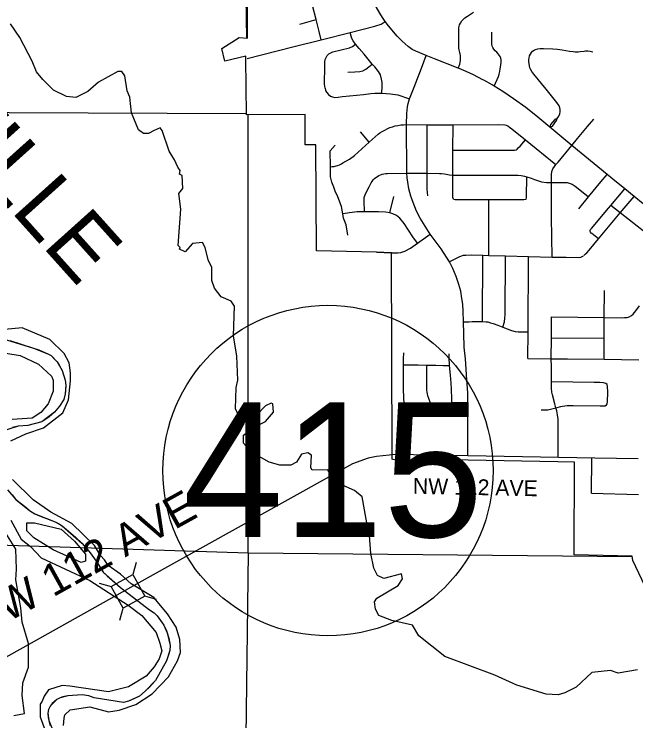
# Model space of a CAD drawing. Extents: x -1403959 to 81668, y -1400582 to 11018.
# Drawn here: x 6553.7 to 6705.6, y 9361 to 9533.5 of the extents above; entities that cross this region are included whole.
import ezdxf

# ---------------------------------------------------------------- set-up
doc = ezdxf.new("R2010")
doc.units = 0
for name, color, linetype in [('tdCiCityCartoExten', 7, 'Continuous'), ('tdCiCityStreetTxt', 7, 'Continuous'), ('tdCiRRCL', 7, 'Continuous'), ('tdCiSectNmbr', 7, 'Continuous'), ('tdCiSectTwpRng', 7, 'Continuous'), ('tdCoCityStreetMajor', 7, 'Continuous'), ('tdCoClipBndry', 7, 'Continuous'), ('tdCoSecRteCL', 7, 'Continuous'), ('tdCoSectNmbr', 7, 'Continuous'), ('tdCoSurfAsphalt', 7, 'Continuous'), ('tdCoSurfBitum', 7, 'Continuous'), ('tdCoSurfConc', 7, 'Continuous'), ('tdCoTwpNameTxt', 7, 'Continuous')]:
    doc.layers.add(name, color=color, linetype=linetype)

msp = doc.modelspace()

# ---------------------------------------------------------------- linework, layer by layer
at = {"layer": 'tdCiCityCartoExten'}
msp.add_lwpolyline([(6642.22, 9475.37), (6645.91, 9475.25)], dxfattribs=at)
at = {"layer": 'tdCiCityStreetTxt'}
for points in [[(6583.49, 9399.66), (6582.67, 9396.75), (6585.62, 9391.47)], [(6574.47, 9394.63), (6577.38, 9393.8), (6582.67, 9396.75)], [(6579.51, 9385.61), (6580.33, 9388.52), (6577.38, 9393.8)], [(6588.47, 9390.66), (6585.62, 9391.47), (6580.33, 9388.52)]]:
    msp.add_lwpolyline(points, dxfattribs=at)
at = {"layer": 'tdCiRRCL'}
msp.add_lwpolyline([(6707.74, 9393.96), (6704.85, 9400.15), (6704.66, 9401.18), (6690.47, 9401.55), (6690.57, 9424.12), (6686.52, 9424.19), (6664.56, 9424.61), (6651.55, 9424.86), (6650.83, 9423.48), (6646.06, 9424.86), (6646.06, 9425.97), (6645.91, 9475.25), (6642.22, 9475.37), (6627.57, 9475.76), (6627.42, 9501.63), (6624.83, 9501.64), (6624.78, 9509.01), (6610.44, 9508.89), (6610.32, 9522.61), (6610.31, 9523.23), (6605.15, 9522.02), (6604.42, 9525.13), (6608.68, 9527.76), (6610.67, 9527.64), (6610.74, 9565.24)], dxfattribs=at)
at = {"layer": 'tdCiSectNmbr'}
for points in [[(6644.37, 9531.72), (6643.86, 9532.43), (6643.31, 9533.31), (6641.35, 9536.66), (6639.96, 9539.04), (6638.83, 9540.49), (6637.41, 9542.06), (6634.5, 9544.62), (6632.79, 9546.21), (6631.47, 9547.73), (6630.64, 9549.07), (6629.81, 9550.83), (6629.23, 9552.48), (6628.94, 9553.79), (6628.79, 9554.95), (6628.69, 9556.1), (6628.65, 9559.75), (6628.66, 9562.74), (6628.73, 9577.13), (6628.79, 9589.35), (6628.81, 9591.2), (6628.8, 9591.55)], [(6654.33, 9523.38), (6651.83, 9524.45), (6650.94, 9524.91), (6649.97, 9525.58), (6648.46, 9526.88), (6647.23, 9528.16), (6645.17, 9530.62), (6644.37, 9531.72)], [(6653.19, 9520.28), (6654.33, 9523.38)], [(6665.88, 9518.69), (6664.09, 9519.51), (6662.4, 9520.24), (6662.17, 9520.33), (6656.37, 9522.59), (6654.33, 9523.37)], [(6649.62, 9509.26), (6649.81, 9510.89), (6649.94, 9511.67), (6650.24, 9512.83), (6651.4, 9515.7), (6653.19, 9520.28)], [(6715.01, 9480.92), (6709.53, 9485.4), (6705.13, 9488.95), (6702.82, 9490.86), (6699.89, 9493.25), (6698.55, 9494.37), (6689.91, 9501.43), (6684.54, 9505.9), (6681.62, 9508.34), (6678.66, 9510.71), (6675.69, 9512.86), (6673.04, 9514.63), (6670.91, 9515.95), (6670.5, 9516.21), (6668.4, 9517.36), (6668.17, 9517.47), (6665.88, 9518.69)], [(6664.49, 9425.7), (6664.52, 9437.42), (6664.49, 9441.03), (6664.31, 9444.24), (6663.91, 9449.39), (6663.65, 9452.23), (6663.52, 9455.58), (6663.43, 9458.38), (6663.38, 9461.01), (6663.27, 9462.74), (6663.09, 9464.13), (6662.79, 9465.86), (6662.36, 9467.48), (6661.68, 9469.48), (6660.84, 9471.41), (6660.03, 9473.08), (6657.97, 9476.21), (6655.36, 9479.83), (6654.09, 9481.76), (6652.9, 9483.67), (6651.98, 9485.41), (6651.15, 9487.49), (6650.59, 9489.11), (6650.11, 9490.84), (6649.85, 9492.46), (6649.68, 9493.58), (6649.6, 9494.65), (6649.52, 9506.54), (6649.62, 9509.26)], [(6645.91, 9475.25), (6647.46, 9475.2), (6648.13, 9475.32), (6649.15, 9475.65), (6650.52, 9476.38), (6652.25, 9477.61), (6655.36, 9479.83)]]:
    msp.add_lwpolyline(points, dxfattribs=at)
at = {"layer": 'tdCiSectTwpRng'}
for points in [[(6628.67, 9527.26), (6628.18, 9529.25), (6627.49, 9532.17), (6626.6, 9535.6), (6625.93, 9538.31), (6624.97, 9541.95), (6624.63, 9543.49), (6624.49, 9544.59), (6624.42, 9545.56), (6624.42, 9546.66), (6624.51, 9547.64), (6624.61, 9548.9), (6624.73, 9550.29), (6624.73, 9551.15), (6624.75, 9554.68), (6624.88, 9565.47), (6624.88, 9577.21)], [(6662.17, 9520.33), (6662.55, 9521.32), (6662.65, 9521.73), (6662.73, 9522.3), (6662.74, 9522.81), (6662.7, 9523.43), (6662.59, 9524.1), (6662.4, 9524.78), (6662.33, 9525.17), (6662.32, 9525.82), (6662.32, 9529.65), (6662.32, 9530.06), (6662.42, 9530.6), (6662.51, 9530.88), (6662.72, 9531.32), (6663.04, 9531.86), (6663.36, 9532.19), (6663.82, 9532.61), (6664.43, 9533), (6665.93, 9533.99)], [(6610.66, 9522.7), (6621.79, 9525.54), (6628.67, 9527.26), (6635.78, 9529.04), (6641.84, 9530.57), (6643.32, 9531.09), (6644.37, 9531.72)], [(6623.51, 9531.03), (6627.49, 9532.17)], [(6670.91, 9515.95), (6671.98, 9518.28), (6672.17, 9518.81), (6672.32, 9519.48), (6672.43, 9520.16), (6672.55, 9521.03), (6672.63, 9521.82), (6672.63, 9522.33), (6672.55, 9522.75), (6672.4, 9523.19), (6672.21, 9523.52), (6671.96, 9523.79), (6671.57, 9524.2), (6671.17, 9524.56), (6670.83, 9524.97), (6670.62, 9525.36), (6670.5, 9525.69), (6670.42, 9526.15), (6670.41, 9527.54), (6670.42, 9529.14)], [(6643.49, 9514.23), (6643.63, 9515.94), (6643.59, 9516.84), (6643.46, 9517.67), (6643.17, 9518.66), (6642.68, 9519.48), (6641.8, 9520.6), (6641.19, 9521.3), (6639.23, 9523.7), (6638.02, 9525.12), (6637.11, 9526.14), (6636.51, 9527), (6636.21, 9527.53), (6636.02, 9528.09), (6635.78, 9529.04)], [(6629.56, 9520.79), (6629.57, 9521.85), (6629.66, 9522.41), (6629.9, 9522.94), (6630.19, 9523.41), (6630.59, 9523.78), (6631.04, 9524.08), (6631.59, 9524.3), (6635.65, 9525.3), (6636.36, 9525.58), (6637.11, 9526.14)], [(6686.32, 9508.04), (6686.73, 9508.61), (6686.98, 9509.16), (6687.09, 9509.69), (6687.09, 9510.21), (6687.02, 9510.67), (6686.83, 9511.14), (6686.26, 9511.95), (6683.64, 9515.16), (6680.66, 9518.82), (6680.16, 9519.5), (6679.83, 9520.04), (6679.67, 9520.43), (6679.54, 9520.91), (6679.46, 9521.45), (6679.42, 9521.88), (6679.42, 9522.37), (6679.47, 9522.87), (6679.6, 9523.32), (6679.79, 9523.74), (6680.06, 9524.15), (6680.33, 9524.44), (6680.68, 9524.72), (6681.03, 9524.88), (6681.61, 9525.07), (6682.16, 9525.13), (6683.01, 9525.12), (6685.24, 9525.03), (6686.4, 9524.94), (6687.52, 9524.8), (6688.48, 9524.63), (6689.33, 9524.5), (6690.22, 9524.38), (6690.77, 9524.33), (6691.47, 9524.33), (6691.97, 9524.35), (6692.9, 9524.46), (6693.25, 9524.52), (6693.82, 9524.52), (6694.42, 9524.48), (6695.05, 9524.29)], [(6695.05, 9524.29), (6695.08, 9524.28)], [(6629.64, 9515.47), (6629.51, 9516.4), (6629.56, 9520.79)], [(6635.19, 9519.37), (6636.95, 9519.44), (6638.12, 9519.49), (6638.91, 9519.69), (6639.58, 9520.05), (6640.37, 9520.64), (6641.19, 9521.3)], [(6629.64, 9515.47), (6629.78, 9514.89), (6629.98, 9514.46), (6630.49, 9513.87), (6631, 9513.51), (6631.5, 9513.32), (6632.02, 9513.18), (6632.83, 9513.26), (6633.91, 9513.37), (6639.01, 9513.92), (6640.79, 9514.12), (6641.79, 9514.23), (6643.49, 9514.23), (6645.66, 9514.02), (6647.44, 9513.78), (6650.24, 9512.83)], [(6686.32, 9508.04), (6685.76, 9507.8), (6684.67, 9506.54), (6684.54, 9505.9)], [(6684.56, 9505.91), (6685.19, 9506.19), (6686.21, 9507.54), (6686.32, 9508.04)], [(6689.91, 9501.43), (6691.33, 9503.15), (6693.74, 9506.07), (6695.31, 9507.86)], [(6630.95, 9496.26), (6631.41, 9496.29), (6631.88, 9496.35), (6632.33, 9496.45), (6632.78, 9496.59), (6633.21, 9496.76), (6633.63, 9496.96), (6634.03, 9497.2), (6635.61, 9498.09), (6636.88, 9499), (6640.44, 9502.23), (6642.64, 9504.18), (6643.06, 9504.49), (6643.63, 9504.88), (6644.22, 9505.22), (6644.84, 9505.53), (6645.47, 9505.8), (6646.12, 9506.03), (6646.79, 9506.22), (6647.46, 9506.36), (6648.14, 9506.47), (6648.83, 9506.52), (6649.52, 9506.54)], [(6649.54, 9506.54), (6654.56, 9506.52), (6658.13, 9506.51)], [(6654.76, 9489.12), (6654.59, 9490.82), (6654.57, 9494.67), (6654.58, 9500.61), (6654.56, 9506.46)], [(6658.13, 9506.51), (6660.91, 9506.51), (6672.09, 9506.53), (6673.55, 9506.51), (6673.92, 9506.44), (6674.3, 9506.27), (6674.73, 9505.95), (6675.26, 9505.52), (6678.57, 9502.84), (6686.05, 9496.81)], [(6661.04, 9488.36), (6660.89, 9488.74), (6660.86, 9489.24), (6660.86, 9494.22), (6660.85, 9500.31), (6660.91, 9506.51)], [(6684.54, 9505.9), (6684.56, 9505.91)], [(6640.44, 9502.23), (6638.33, 9504.74)], [(6635.24, 9479.59), (6634.77, 9482.08), (6634.16, 9483.7), (6634.02, 9484.76), (6633.68, 9486.54), (6632.76, 9488.87), (6632.15, 9490.27), (6631.76, 9491.27), (6631.31, 9492.51), (6630.97, 9493.8), (6630.95, 9496.26), (6630.92, 9500.14), (6632.09, 9501.5)], [(6660.85, 9500.31), (6675.37, 9500.26), (6675.92, 9500.3), (6676.29, 9500.35), (6676.6, 9500.55), (6676.84, 9500.83), (6677.27, 9501.3), (6678.57, 9502.84)], [(6685.1, 9474.21), (6684.98, 9483.93), (6684.94, 9486.33), (6684.96, 9492.4), (6684.93, 9494.37), (6685.05, 9495.09), (6685.28, 9495.74), (6685.65, 9496.33), (6686.05, 9496.81), (6686.54, 9497.36), (6689.91, 9501.43)], [(6639.17, 9488), (6639.23, 9488.71), (6639.54, 9489.65), (6640.4, 9491.33), (6640.92, 9492.32), (6641.16, 9492.69), (6641.43, 9493.03), (6641.73, 9493.35), (6642.06, 9493.63), (6642.42, 9493.89), (6642.79, 9494.11), (6643.19, 9494.29), (6643.6, 9494.44), (6644.03, 9494.55), (6644.46, 9494.61), (6644.9, 9494.64), (6649.6, 9494.65)], [(6649.65, 9494.65), (6654.57, 9494.67), (6657.56, 9494.62)], [(6657.56, 9494.62), (6658.08, 9494.61), (6658.83, 9494.56), (6660.01, 9494.3), (6660.86, 9494.22), (6676.76, 9494.2), (6677.58, 9494.11), (6678.37, 9493.99), (6678.96, 9493.81), (6680.01, 9493.43), (6680.83, 9493.12), (6682.52, 9492.59), (6683.71, 9492.44), (6684.96, 9492.4), (6688.2, 9492.4), (6688.75, 9492.39), (6689.3, 9492.25), (6690.02, 9491.98), (6690.77, 9491.53), (6691.49, 9490.95), (6694, 9488.89)], [(6678.74, 9488.33), (6678.84, 9488.65), (6678.88, 9489), (6678.96, 9493.81)], [(6691.61, 9485.96), (6694, 9488.89), (6697.01, 9492.61), (6698.55, 9494.37)], [(6694.78, 9479.92), (6694.6, 9480.07), (6694.46, 9480.26), (6694.41, 9480.46), (6694.4, 9480.68), (6694.51, 9480.93), (6694.72, 9481.2), (6698.89, 9486.11), (6699.48, 9486.8), (6702.82, 9490.86)], [(6639.27, 9485.26), (6639.17, 9488)], [(6645.48, 9485.02), (6646.47, 9488.96)], [(6661.04, 9488.36), (6661.46, 9488.24), (6661.95, 9488.22), (6669.64, 9488.23), (6677.74, 9488.22), (6678.22, 9488.23), (6678.74, 9488.33)], [(6669.62, 9474.61), (6669.64, 9488.23)], [(6692.82, 9474.55), (6693.21, 9474.88), (6693.56, 9475.25), (6694.11, 9475.86), (6696.44, 9478.65), (6701.7, 9485.01), (6705.13, 9488.95)], [(6719.41, 9470.65), (6715.54, 9473.82), (6711.88, 9476.99), (6701.7, 9485.01), (6699.48, 9486.8)], [(6634.06, 9484.77), (6634.02, 9484.76)], [(6652.25, 9477.61), (6651.06, 9479.18), (6648.95, 9482.4), (6647.89, 9483.7), (6647.06, 9484.33), (6646.17, 9484.78), (6645.48, 9485.02), (6644.43, 9485.18), (6642.7, 9485.24), (6639.27, 9485.26), (6637.47, 9485.24), (6635.66, 9484.98), (6634.06, 9484.77)], [(6696.44, 9478.65), (6694.78, 9479.92)], [(6660.09, 9473.11), (6662.54, 9474.35), (6663.5, 9474.7), (6664.01, 9474.69), (6665.32, 9474.73), (6668.15, 9474.67)], [(6668.11, 9458.45), (6668.15, 9474.67)], [(6668.15, 9474.67), (6669.62, 9474.61), (6673.68, 9474.53), (6679.31, 9474.36), (6685.1, 9474.21), (6688.55, 9474.18)], [(6673.09, 9457.12), (6673.47, 9458.39), (6673.59, 9459.3), (6673.64, 9460.08), (6673.68, 9474.53)], [(6679.2, 9449.44), (6679.29, 9455.95), (6679.31, 9474.36)], [(6688.55, 9474.18), (6691.63, 9474.13), (6692.09, 9474.18), (6692.43, 9474.31), (6692.79, 9474.52)], [(6697.79, 9449.32), (6697.78, 9454.38), (6697.78, 9459.43), (6697.86, 9466.07)], [(6684.93, 9459.61), (6697.78, 9459.43), (6702.04, 9459.4), (6702.8, 9459.42), (6703.39, 9459.49), (6703.9, 9459.63), (6704.45, 9459.91), (6704.91, 9460.27), (6705.54, 9461.11), (6706.47, 9462.33)], [(6663.43, 9458.38), (6663.6, 9458.39)], [(6663.6, 9458.39), (6664.73, 9458.42)], [(6664.73, 9458.42), (6665.54, 9458.44), (6668.11, 9458.45), (6668.97, 9458.43), (6669.43, 9458.37), (6670.03, 9458.19), (6670.71, 9458.02), (6671.82, 9457.62), (6673.09, 9457.12), (6675.18, 9456.31), (6676.09, 9456.04), (6676.82, 9455.99), (6679.29, 9455.95)], [(6684.84, 9449.38), (6684.97, 9454.51), (6684.93, 9459.61)], [(6684.97, 9454.51), (6697.78, 9454.38)], [(6649.13, 9437.75), (6648.92, 9439.41), (6648.86, 9440.13), (6648.81, 9441.84), (6648.81, 9443.82), (6648.83, 9447.93), (6648.83, 9449.34), (6648.85, 9450.85)], [(6660.61, 9438.15), (6660.6, 9438.67), (6660.61, 9440.24), (6660.57, 9441.2), (6660.55, 9441.96), (6660.46, 9443.44), (6660.3, 9445.36), (6660.08, 9447.77), (6659.96, 9449.77), (6659.92, 9450.62)], [(6679.2, 9449.44), (6684.84, 9449.38)], [(6684.84, 9449.38), (6688.84, 9449.4), (6697.79, 9449.32), (6706.26, 9449.15)], [(6686.54, 9425.29), (6686.59, 9429.83), (6686.59, 9433.48), (6686.54, 9434.67), (6686.45, 9435.69), (6686.23, 9436.7), (6686.04, 9437.42), (6685.78, 9438.39), (6685.21, 9440.54), (6685.06, 9441.2), (6684.94, 9442.23), (6684.94, 9443.04), (6684.95, 9443.73), (6684.97, 9445.05), (6684.92, 9447.48), (6684.84, 9449.38), (6684.84, 9449.38)], [(6648.83, 9447.93), (6650.31, 9447.92), (6652.4, 9447.91), (6654.52, 9447.84), (6656.74, 9447.81), (6658.52, 9447.75), (6660.08, 9447.77)], [(6655.4, 9438.56), (6655, 9439.7), (6654.79, 9440.31), (6654.64, 9440.82), (6654.57, 9441.27), (6654.5, 9441.74), (6654.47, 9442.69), (6654.48, 9446.22), (6654.52, 9447.84)], [(6682.44, 9436.91), (6683.44, 9436.89), (6684.04, 9436.93), (6684.42, 9436.98), (6685.37, 9437.24), (6686.04, 9437.42), (6687.23, 9437.72), (6687.64, 9437.82), (6688.19, 9437.91), (6688.81, 9437.98), (6690.21, 9437.98), (6696.82, 9437.87), (6697.75, 9437.89), (6698.09, 9437.91), (6698.4, 9438.13), (6698.56, 9438.37), (6698.63, 9438.84), (6698.68, 9441.23), (6698.61, 9442.68), (6698.52, 9443.14), (6698.21, 9443.35), (6697.66, 9443.49), (6696.75, 9443.57), (6695.37, 9443.57), (6684.95, 9443.73)], [(6660.6, 9438.67), (6662.44, 9438.67), (6664.51, 9438.67)], [(6694.73, 9416.54), (6694.84, 9425.13)], [(6694.73, 9416.54), (6706.22, 9416.24)]]:
    msp.add_lwpolyline(points, dxfattribs=at)
at = {"layer": 'tdCoCityStreetMajor'}
for points in [[(6610.55, 9527.64), (6609.42, 9597.47)], [(6513.8, 9509.68), (6610.4, 9509.24)], [(6610.87, 9402.01), (6610.86, 9508.39), (6610.85, 9508.9)], [(6511.21, 9405.21), (6610.87, 9402.01)], [(6610.87, 9402.01), (6609.63, 9305.79)], [(6610.87, 9402.01), (6704.63, 9401.12)]]:
    msp.add_lwpolyline(points, dxfattribs=at)
at = {"layer": 'tdCoClipBndry'}
for points in [[(6551.07, 9454.21), (6558.42, 9452.01), (6562.08, 9450.54), (6562.74, 9450.16), (6564.22, 9448.64), (6565.45, 9446.53), (6566.16, 9444.17), (6566.33, 9442.92), (6566.16, 9440.79), (6565.85, 9439.44), (6564.81, 9437.79), (6563.58, 9436.33), (6560.48, 9433.98), (6557.09, 9433.09), (6554.71, 9432.93), (6550.37, 9431.54)], [(6552.09, 9417.41), (6554.16, 9415.04), (6557.51, 9412.32), (6558.75, 9411.54), (6563.72, 9409.58), (6565.43, 9408.64), (6570.27, 9404.4), (6572.08, 9402.33), (6574, 9399.66), (6575.44, 9397.26), (6579.73, 9393.53), (6586.79, 9388.14), (6587.92, 9387.36), (6588.69, 9386.65), (6590.24, 9384.39), (6591.1, 9382.51), (6591.8, 9379.38), (6591.72, 9378.17), (6590.92, 9375.68), (6588.27, 9370.85), (6585.75, 9368.23), (6584.3, 9367.03), (6581.61, 9365.81), (6580.44, 9365.52), (6573.26, 9366.66), (6571.94, 9367.08), (6570.37, 9367.35), (6566.8, 9367.09), (6564.97, 9366.63), (6564.15, 9366.2), (6562.49, 9364.6), (6562.08, 9363.8), (6561.96, 9362.88), (6562.16, 9361.11), (6563.66, 9357.49)]]:
    msp.add_lwpolyline(points, dxfattribs=at)
at = {"layer": 'tdCoSecRteCL'}
msp.add_lwpolyline([(6706.14, 9424.94), (6695.52, 9425.1), (6646.83, 9426.05), (6642.24, 9425.54), (6640.19, 9425.12), (6636.32, 9423.72), (6586.24, 9395.82), (6555.85, 9378.84), (6530.4, 9364.67)], dxfattribs=at)
at = {"layer": 'tdCoSurfAsphalt'}
msp.add_circle((6630.36, 9422.1), 40.33, dxfattribs=at)
at = {"layer": 'tdCoSurfBitum'}
for points in [[(6705.96, 9373.43), (6701.22, 9372.68), (6699.39, 9373.29), (6694.81, 9372.84), (6690.99, 9369.19), (6688.23, 9367.82), (6686.55, 9367.37), (6683.65, 9367.53), (6676.48, 9369.68), (6671.14, 9372.13), (6658.94, 9376.74), (6652.53, 9381.79), (6651.01, 9384.39), (6645.97, 9385.47), (6642.77, 9386.7), (6642.01, 9388.23), (6641.71, 9390.06), (6642.32, 9390.98), (6647.52, 9394.02), (6648.59, 9395.7), (6648.29, 9396.92), (6644.01, 9395.71), (6642.48, 9396.47), (6641.57, 9398.31), (6640.82, 9401.82), (6640.52, 9406.25), (6640.07, 9407.93), (6638.71, 9415.72), (6636.88, 9417.25), (6632.61, 9419.09), (6631.24, 9420.77), (6630.32, 9422.3), (6626.5, 9422.16), (6626.2, 9422.77), (6626.36, 9425.82), (6625.44, 9426.43), (6623.92, 9426.13), (6622.69, 9424.15), (6621.32, 9423.39), (6618.57, 9423.4), (6615.97, 9424.16), (6611.7, 9426.62), (6609.72, 9428.76), (6609.73, 9430.74), (6612.17, 9432.57), (6615.08, 9434.09), (6617.07, 9436.37), (6616.92, 9438.36), (6616.46, 9438.51), (6615.08, 9437.91), (6613.09, 9435.77), (6611.11, 9435.17), (6609.43, 9435.32), (6608.36, 9435.94), (6607.75, 9437.16), (6607.92, 9442.35), (6608.38, 9444.18), (6608.09, 9449.98), (6607.33, 9455.02), (6607.5, 9462.2), (6606.74, 9463.42), (6604.3, 9464.49), (6602.62, 9466.63), (6602.02, 9468.47), (6602.02, 9471.67), (6601.11, 9473.51), (6600.35, 9476.56), (6599.74, 9477.79), (6597.3, 9477.49), (6595.46, 9475.51), (6594.09, 9476.12), (6594.25, 9476.58), (6593.79, 9477.04), (6594.42, 9485.89), (6593.97, 9489.71), (6594.89, 9490.92), (6594.74, 9494.13), (6594.13, 9494.44), (6594.28, 9495.35), (6593.68, 9496.12), (6592.92, 9497.95), (6591.55, 9500.09), (6589.88, 9505.13), (6589.42, 9505.75), (6587.89, 9505.14), (6586.52, 9504.38), (6585.29, 9504.38), (6584.07, 9505.3), (6582.4, 9509.43), (6581.95, 9513.24), (6581.35, 9514.77), (6580.74, 9518.44), (6579.98, 9519.51), (6579.06, 9519.51), (6574.33, 9516.92), (6571.73, 9514.64), (6568.82, 9513.12), (6566.53, 9513.43), (6563.33, 9514.96), (6560.74, 9517.57), (6559.21, 9519.4), (6558.15, 9522), (6555.11, 9527.81), (6552.83, 9531.17)], [(6552.92, 9429.35), (6556.59, 9431.02), (6560.87, 9432.53), (6565.61, 9436.19), (6566.99, 9439.39), (6567.46, 9443.97), (6567.46, 9445.95), (6567.16, 9448.4), (6565.94, 9450.69), (6562.44, 9454.06), (6555.72, 9456.97), (6551.45, 9456.52)], [(6551.7, 9450.79), (6555.21, 9450.17), (6559.63, 9448.03), (6562.83, 9445.12), (6563.29, 9444.2), (6563.29, 9441.45), (6562.06, 9438.39), (6560.23, 9436.25), (6558.1, 9434.87), (6553.22, 9434.56)], [(6565.75, 9359.86), (6565.91, 9361.69), (6566.06, 9362.45), (6567.44, 9363.67), (6572.18, 9364.42), (6576.75, 9363.19), (6579.35, 9363.64), (6583.48, 9365.01), (6587.45, 9367.59), (6591.43, 9371.71), (6593.58, 9375.67), (6594.35, 9377.65), (6594.2, 9380.86), (6593.29, 9383.91), (6591.16, 9387.12), (6587.81, 9391.1), (6582.32, 9394.47), (6579.73, 9396.77), (6576.68, 9398.91), (6575.76, 9400.29), (6574.85, 9401.36), (6573.33, 9403.81), (6567.84, 9409.16), (6562.65, 9411.92), (6558.39, 9414.98), (6553.36, 9419.88)], [(6553.68, 9362.33), (6556.27, 9362.78), (6555.66, 9367.21), (6555.81, 9370.26), (6557.19, 9374.08), (6557.19, 9379.88), (6555.66, 9385.07), (6555.35, 9388.58), (6554.13, 9395.45), (6554.28, 9398.05), (6554.13, 9402.93), (6550.46, 9408.74)], [(6552.88, 9409.96), (6555.46, 9405.37), (6557.75, 9403.54), (6560.34, 9400.78), (6572.24, 9395.26), (6581.54, 9389.28), (6584.9, 9386.68), (6588.4, 9382.55), (6589.31, 9379.95), (6589.76, 9378.12), (6589.15, 9376.14), (6587.92, 9374.16), (6585.93, 9371.87), (6581.65, 9369.29), (6576.76, 9368.07), (6567.3, 9369.47), (6565.47, 9369.63), (6562.11, 9368.57), (6561.03, 9367.04), (6560.57, 9365.82), (6560.11, 9365.06), (6560.11, 9362.01), (6561.02, 9359.26)], [(6570.11, 9399.69), (6563.25, 9402.76), (6558.52, 9405.67), (6556.84, 9407.35), (6556.85, 9409.34), (6558.68, 9409.33), (6565.24, 9407.79), (6568.44, 9404.89), (6571.18, 9401.67), (6571.18, 9399.99), (6570.11, 9399.69)]]:
    msp.add_lwpolyline(points, dxfattribs=at)
at = {"layer": 'tdCoTwpNameTxt'}
for points in [[(6552.65, 9453.83), (6558.42, 9452.01), (6559.74, 9451.55), (6562.08, 9450.54), (6562.74, 9450.16), (6563.53, 9449.38), (6564.22, 9448.64), (6564.69, 9447.83), (6565.45, 9446.53), (6566.16, 9444.17), (6566.33, 9442.92), (6566.28, 9441.56), (6566.16, 9440.79), (6565.85, 9439.44), (6564.81, 9437.79), (6563.58, 9436.33), (6562.25, 9435.21), (6560.48, 9433.98), (6557.09, 9433.09), (6554.71, 9432.93), (6553.35, 9432.61)], [(6553.22, 9416.18), (6554.16, 9415.04), (6556.56, 9413.14), (6557.51, 9412.32), (6558.75, 9411.54), (6559.95, 9411.01), (6563.72, 9409.58), (6564.56, 9409.2), (6565.43, 9408.64), (6566.96, 9407.34), (6568.74, 9405.81), (6570.27, 9404.4), (6572.08, 9402.33)], [(6572.08, 9402.33), (6574, 9399.66), (6574.9, 9398.14), (6575.44, 9397.26), (6576.42, 9396.4), (6579.73, 9393.53), (6586.79, 9388.14), (6587.92, 9387.36), (6588.69, 9386.65), (6590.24, 9384.39), (6590.82, 9383.21), (6591.1, 9382.51), (6591.49, 9381.22), (6591.8, 9379.38), (6591.72, 9378.17), (6591.41, 9377.1), (6590.92, 9375.68), (6588.27, 9370.85), (6586.78, 9369.21), (6585.75, 9368.23), (6584.3, 9367.03), (6582.94, 9366.35), (6581.61, 9365.81), (6580.44, 9365.52), (6573.26, 9366.66), (6571.94, 9367.08), (6570.37, 9367.35), (6566.8, 9367.09), (6565.63, 9366.85), (6564.97, 9366.63), (6564.15, 9366.2), (6563.04, 9365.22), (6562.49, 9364.6), (6562.08, 9363.8), (6561.96, 9362.88), (6562.05, 9361.7), (6562.16, 9361.11), (6562.55, 9359.89)]]:
    msp.add_lwpolyline(points, dxfattribs=at)

# ---------------------------------------------------------------- texts
at = {"layer": 'tdCoSectNmbr'}
for height, rotation, p in [(3.869, 358.8514, (6651.07, 9416.43)), (7.738, 28.9784, (6545.61, 9381.37))]:
    msp.add_text('NW 112 AVE', height=height, rotation=rotation, dxfattribs=at).set_placement(p)
at = {"layer": 'tdCoSurfAsphalt'}
msp.add_text('415', height=32.887, dxfattribs=at).set_placement((6594.95, 9405.87))
at = {"layer": 'tdCoSurfConc'}
msp.add_text('SAYLORVILLE', height=15.4765, rotation=311.9085, dxfattribs=at).set_placement((6475.82, 9571.11))

doc.saveas('drawing.dxf')
